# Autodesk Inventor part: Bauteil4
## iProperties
Shininess: 64.0
Length Units: 11269
Angle Units: 11279
Time Units: 11290
Mass Units: 11283
Length Display Precision: 3
Angle Display Precision: 2
Compacted: True
Part Number: Bauteil4
Document SubType Name: Modeling
Created: 2003-09
Material: Standard
Cost Center: 0.004 kg
Authority: 3758.2 mm^3
Designer: juergen
Density: 0.0
Volumn: 0.0
Area: 0.0
PropertySet Name: Model Information
Control State: 0
Master: False
Checked Out: False
SaveDate: 2003-09-14
SaveTime: 15:27
TotalMass: 0.004 kg
TotalVolume: 3758.2 mm^3
Author: juergen
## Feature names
1. Extrusion1
2. Erhebung1
3. Spiegeln1 [Mirror]
